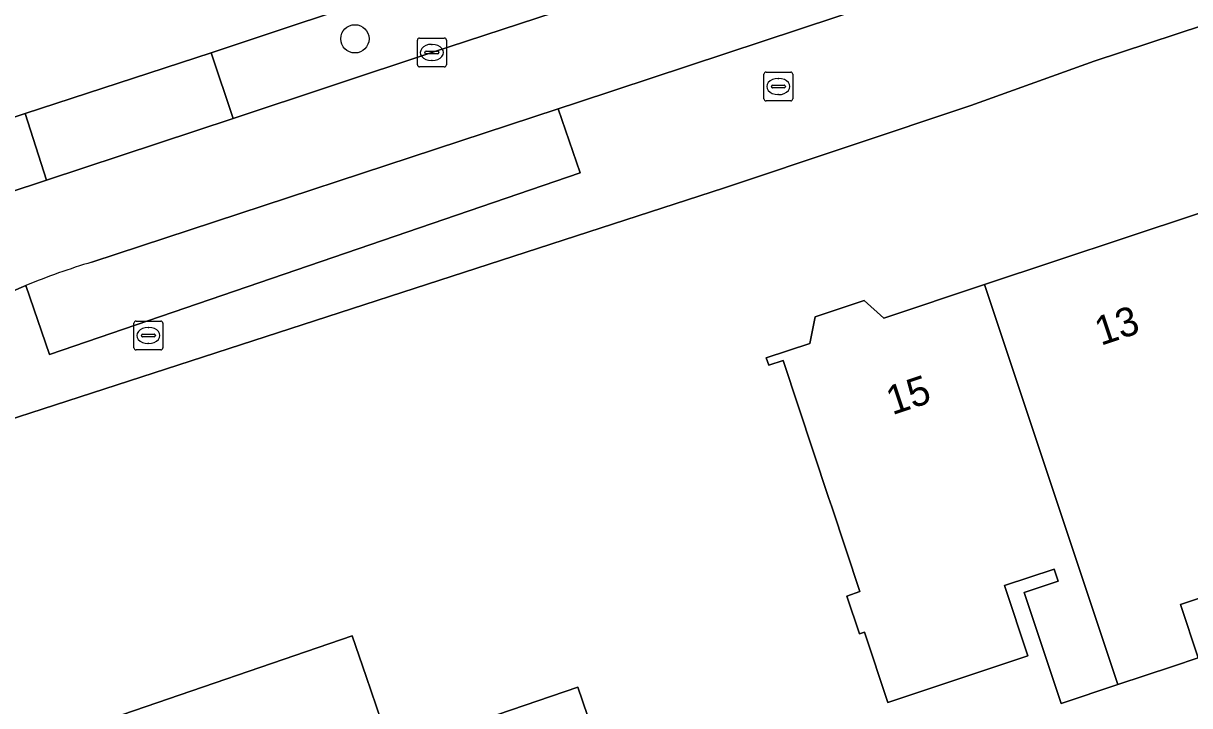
# Model space of a CAD drawing. Extents: x 161087 to 161926, y 382572 to 383873.
# Drawn here: x 161600.37 to 161640.73, y 382757.68 to 382781.29 of the extents above; entities that cross this region are included whole.
import ezdxf

# ---------------------------------------------------------------- set-up
doc = ezdxf.new("R2010")
doc.units = 0
for name, color, linetype in [('IMGEO_Berm_groen', 7, 'Continuous'), ('IMGEO_Boom', 7, 'Continuous'), ('IMGEO_Brandkraan', 7, 'Continuous'), ('IMGEO_Erf', 7, 'Continuous'), ('IMGEO_Fietspad_gesloten', 7, 'Continuous'), ('IMGEO_Kolk', 7, 'Continuous'), ('IMGEO_Muur', 7, 'Continuous'), ('IMGEO_Pand', 7, 'Continuous'), ('IMGEO_Pand_nummerreeks', 7, 'Continuous'), ('IMGEO_Rijbaan_lokaal_gesloten', 7, 'Continuous'), ('IMGEO_Rioolput', 7, 'Continuous'), ('IMGEO_Voetpad_halfverhard', 7, 'Continuous'), ('IMGEO_Voetpad_open', 7, 'Continuous')]:
    doc.layers.add(name, color=color, linetype=linetype)

msp = doc.modelspace()

# ---------------------------------------------------------------- linework, layer by layer
at = {"layer": 'IMGEO_Berm_groen'}
msp.add_lwpolyline([(161621.173, 382782.476), (161620.39, 382784.782), (161606.867, 382780.274), (161607.628, 382778.007), (161614.505, 382780.286)], close=True, dxfattribs=at)
for points in [[(161619.632, 382776.119), (161618.873, 382778.339), (161602.74, 382773.032)], [(161599.806, 382775.416), (161601.167, 382775.867), (161600.424, 382778.175), (161590.845, 382774.955)], [(161600.455, 382772.219), (161601.27, 382769.836), (161619.632, 382776.119)]]:
    msp.add_lwpolyline(points, dxfattribs=at)
msp.add_arc((161609.005, 382751.807), 22.13, 106.4443, 112.7267, dxfattribs=at)
at = {"layer": 'IMGEO_Boom'}
msp.add_circle((161611.84, 382780.758), 0.489, dxfattribs=at)
at = {"layer": 'IMGEO_Brandkraan'}
for p, q in [((161604.193, 382770.067), (161604.193, 382770.919)), ((161604.268, 382770.993), (161605.12, 382770.993)), ((161604.681, 382770.773), (161604.706, 382770.773)), ((161605.194, 382770.919), (161605.194, 382770.067)), ((161604.452, 382770.487), (161604.452, 382770.499)), ((161604.89, 382770.45), (161604.492, 382770.45)), ((161604.495, 382770.536), (161604.893, 382770.536)), ((161604.936, 382770.499), (161604.936, 382770.487)), ((161605.12, 382769.993), (161604.268, 382769.993)), ((161604.704, 382770.213), (161604.679, 382770.213))]:
    msp.add_line(p, q, dxfattribs=at)
for points in [[(161604.193, 382770.067), (161604.193, 382770.919)], [(161604.268, 382770.993), (161605.12, 382770.993)], [(161605.194, 382770.919), (161605.194, 382770.067)], [(161605.12, 382769.993), (161604.268, 382769.993)]]:
    msp.add_lwpolyline(points, dxfattribs=at)
for centre, radius, start, end in [((161604.27, 382770.917), 0.0765, 91.552, 178.448), ((161604.27, 382770.917), 0.0765, 91.552, 178.448), ((161605.118, 382770.917), 0.0765, 1.552, 88.448), ((161605.118, 382770.917), 0.0765, 1.552, 88.448), ((161604.492, 382770.496), 0.0403, 85.8775, 175.7526), ((161604.489, 382770.486), 0.0366, 178.938, 274.7102), ((161604.893, 382770.493), 0.043, 264.8664, 352.4533), ((161604.897, 382770.498), 0.0386, 1.7309, 96.639), ((161604.27, 382770.069), 0.0765, 181.552, 268.448), ((161604.27, 382770.069), 0.0765, 181.552, 268.448), ((161605.118, 382770.069), 0.0765, 271.552, 358.448), ((161605.118, 382770.069), 0.0765, 271.552, 358.448)]:
    msp.add_arc(centre, radius, start, end, dxfattribs=at)
for centre, major_axis, ratio, start_param, end_param in [((161604.68, 382770.493), (-0.387, 0.002), 0.722429, 4.712389, 7.853982), ((161604.705, 382770.493), (-0.39, 0.002), 0.717154, 1.570796, 4.712389)]:
    msp.add_ellipse(centre, major_axis=major_axis, ratio=ratio, start_param=start_param, end_param=end_param, dxfattribs=at)
at = {"layer": 'IMGEO_Erf'}
for points in [[(161667.594, 382789.929), (161637.427, 382779.982), (161633.162, 382778.456), (161624.636, 382775.599), (161601.023, 382767.942), (161596.158, 382766.372), (161596.018, 382766.327), (161595.848, 382766.199), (161596.009, 382765.952), (161595.696, 382765.813), (161595.594, 382766.012), (161590.565, 382762.379), (161588.667, 382761.008), (161586.678, 382759.589), (161585.017, 382758.404), (161585.099, 382758.295), (161583.93, 382757.469)], [(161644.492, 382762.54), (161640.411, 382761.181), (161641.024, 382759.339), (161640.133, 382759.042), (161638.239, 382758.411), (161636.283, 382757.76), (161635.004, 382761.604), (161636.175, 382761.994), (161636.037, 382762.407), (161634.326, 382761.838), (161635.133, 382759.413), (161630.282, 382757.798), (161629.474, 382760.224), (161629.3, 382760.166), (161628.864, 382761.475), (161629.318, 382761.634), (161628.343, 382764.561), (161628.236, 382764.882), (161626.657, 382769.626), (161626.163, 382769.462), (161626.079, 382769.715), (161627.585, 382770.216), (161627.773, 382771.134), (161629.469, 382771.698), (161630.151, 382771.093), (161633.634, 382772.252), (161641.001, 382774.705)]]:
    msp.add_lwpolyline(points, dxfattribs=at)
msp.add_lwpolyline([(161626.489, 382746.857), (161625.734, 382746.594), (161625.299, 382747.84), (161621.008, 382746.343), (161621.443, 382745.096), (161621.131, 382744.988), (161621.665, 382743.458), (161605.682, 382737.882), (161602.665, 382746.708), (161606.548, 382748.035), (161606.513, 382748.138), (161605.876, 382750), (161605.018, 382752.511), (161603.401, 382757.242), (161611.749, 382760.095), (161612.227, 382758.695), (161612.749, 382757.17), (161613.106, 382756.121), (161619.557, 382758.324), (161621.59, 382752.37), (161624.249, 382753.278)], close=True, dxfattribs=at)
at = {"layer": 'IMGEO_Fietspad_gesloten'}
msp.add_lwpolyline([(161590.845, 382774.955), (161600.424, 382778.175), (161606.867, 382780.274), (161620.39, 382784.782), (161636.138, 382789.999), (161645.193, 382792.972), (161647.376, 382793.71), (161647.995, 382793.914), (161673.571, 382802.349), (161674.047, 382802.506), (161679.239, 382804.225), (161681.775, 382805.065), (161703.785, 382812.521), (161709.459, 382814.438)], dxfattribs=at)
at = {"layer": 'IMGEO_Kolk'}
for p, q in [((161614.004, 382779.86), (161614.004, 382780.712)), ((161614.079, 382780.786), (161614.931, 382780.786)), ((161615.005, 382780.712), (161615.005, 382779.86)), ((161614.306, 382780.329), (161614.704, 382780.329)), ((161614.492, 382780.566), (161614.517, 382780.566)), ((161614.263, 382780.28), (161614.263, 382780.292)), ((161614.701, 382780.243), (161614.303, 382780.243)), ((161614.515, 382780.006), (161614.49, 382780.006)), ((161614.747, 382780.292), (161614.747, 382780.28)), ((161614.931, 382779.786), (161614.079, 382779.786))]:
    msp.add_line(p, q, dxfattribs=at)
for points in [[(161614.004, 382779.86), (161614.004, 382780.712)], [(161614.079, 382780.786), (161614.931, 382780.786)], [(161615.005, 382780.712), (161615.005, 382779.86)], [(161614.931, 382779.786), (161614.079, 382779.786)]]:
    msp.add_lwpolyline(points, dxfattribs=at)
for centre, radius, start, end in [((161614.081, 382780.71), 0.0765, 91.552, 178.448), ((161614.081, 382780.71), 0.0765, 91.552, 178.448), ((161614.929, 382780.71), 0.0765, 1.552, 88.448), ((161614.929, 382780.71), 0.0765, 1.552, 88.448), ((161614.303, 382780.289), 0.0403, 85.8775, 175.7526), ((161614.708, 382780.291), 0.0386, 1.7309, 96.639), ((161614.3, 382780.279), 0.0366, 178.938, 274.7102), ((161614.704, 382780.286), 0.043, 264.8664, 352.4533), ((161614.081, 382779.862), 0.0765, 181.552, 268.448), ((161614.081, 382779.862), 0.0765, 181.552, 268.448), ((161614.929, 382779.862), 0.0765, 271.552, 358.448), ((161614.929, 382779.862), 0.0765, 271.552, 358.448)]:
    msp.add_arc(centre, radius, start, end, dxfattribs=at)
for centre, major_axis, ratio, start_param, end_param in [((161614.491, 382780.286), (-0.387, 0.002), 0.722429, 4.712389, 7.853982), ((161614.516, 382780.286), (-0.39, 0.002), 0.717154, 1.570796, 4.712389)]:
    msp.add_ellipse(centre, major_axis=major_axis, ratio=ratio, start_param=start_param, end_param=end_param, dxfattribs=at)
at = {"layer": 'IMGEO_Muur'}
msp.add_lwpolyline([(161601.023, 382767.942), (161624.636, 382775.599)], dxfattribs=at)
at = {"layer": 'IMGEO_Pand'}
for points in [[(161643.603, 382769.478), (161643.358, 382770.215), (161641.778, 382774.958), (161641.001, 382774.705), (161633.634, 382772.252), (161638.239, 382758.411), (161640.133, 382759.042), (161641.024, 382759.339), (161640.411, 382761.181), (161644.492, 382762.54), (161643.696, 382764.929), (161644.2, 382765.097), (161644.979, 382765.344)], [(161633.634, 382772.252), (161630.151, 382771.093), (161629.469, 382771.698), (161627.773, 382771.134), (161627.585, 382770.216), (161626.079, 382769.715), (161626.163, 382769.462), (161626.657, 382769.626), (161628.236, 382764.882), (161628.343, 382764.561), (161629.318, 382761.634), (161628.864, 382761.475), (161629.3, 382760.166), (161629.474, 382760.224), (161630.282, 382757.798), (161635.133, 382759.413), (161634.326, 382761.838), (161636.037, 382762.407), (161636.175, 382761.994), (161635.004, 382761.604), (161636.283, 382757.76), (161638.239, 382758.411)], [(161624.249, 382753.278), (161621.59, 382752.37), (161619.557, 382758.324), (161613.106, 382756.121), (161612.749, 382757.17), (161612.227, 382758.695), (161611.749, 382760.095), (161603.401, 382757.242), (161605.018, 382752.511), (161605.876, 382750), (161606.513, 382748.138), (161606.548, 382748.035), (161602.665, 382746.708), (161605.682, 382737.882), (161621.665, 382743.458), (161621.131, 382744.988), (161621.443, 382745.096), (161621.008, 382746.343), (161625.299, 382747.84), (161625.734, 382746.594), (161626.489, 382746.857)]]:
    msp.add_lwpolyline(points, close=True, dxfattribs=at)
at = {"layer": 'IMGEO_Rijbaan_lokaal_gesloten'}
for points in [[(161602.74, 382773.032), (161618.873, 382778.339), (161619.539, 382778.558), (161637.495, 382784.499), (161640.402, 382785.458), (161656.819, 382790.909)], [(161645.919, 382790.64), (161636.843, 382787.626), (161630.206, 382785.442), (161626.567, 382784.247), (161621.173, 382782.476), (161614.505, 382780.286), (161607.628, 382778.007), (161601.167, 382775.867), (161599.806, 382775.416), (161588.34, 382771.632)], [(161599.434, 382771.772), (161599.942, 382772.001), (161600.455, 382772.219)]]:
    msp.add_lwpolyline(points, dxfattribs=at)
msp.add_arc((161609.005, 382751.807), 22.13, 106.4443, 112.7267, dxfattribs=at)
at = {"layer": 'IMGEO_Rioolput'}
for p, q in [((161625.995, 382778.682), (161625.995, 382779.534)), ((161626.07, 382779.608), (161626.922, 382779.608)), ((161626.996, 382779.534), (161626.996, 382778.682)), ((161626.254, 382779.102), (161626.254, 382779.114)), ((161626.297, 382779.151), (161626.695, 382779.151)), ((161626.483, 382779.388), (161626.508, 382779.388)), ((161626.738, 382779.114), (161626.738, 382779.102)), ((161626.692, 382779.065), (161626.294, 382779.065)), ((161626.506, 382778.828), (161626.481, 382778.828)), ((161626.922, 382778.608), (161626.07, 382778.608))]:
    msp.add_line(p, q, dxfattribs=at)
for points in [[(161625.995, 382778.682), (161625.995, 382779.534)], [(161626.07, 382779.608), (161626.922, 382779.608)], [(161626.996, 382779.534), (161626.996, 382778.682)], [(161626.922, 382778.608), (161626.07, 382778.608)]]:
    msp.add_lwpolyline(points, dxfattribs=at)
for centre, radius, start, end in [((161626.072, 382779.532), 0.0765, 91.552, 178.448), ((161626.072, 382779.532), 0.0765, 91.552, 178.448), ((161626.92, 382779.532), 0.0765, 1.552, 88.448), ((161626.92, 382779.532), 0.0765, 1.552, 88.448), ((161626.294, 382779.111), 0.0403, 85.8775, 175.7526), ((161626.291, 382779.101), 0.0366, 178.938, 274.7102), ((161626.695, 382779.108), 0.043, 264.8664, 352.4533), ((161626.699, 382779.113), 0.0386, 1.7309, 96.639), ((161626.072, 382778.684), 0.0765, 181.552, 268.448), ((161626.072, 382778.684), 0.0765, 181.552, 268.448), ((161626.92, 382778.684), 0.0765, 271.552, 358.448), ((161626.92, 382778.684), 0.0765, 271.552, 358.448)]:
    msp.add_arc(centre, radius, start, end, dxfattribs=at)
for centre, major_axis, ratio, start_param, end_param in [((161626.482, 382779.108), (-0.387, 0.002), 0.722429, 4.712389, 7.853982), ((161626.507, 382779.108), (-0.39, 0.002), 0.717154, 1.570796, 4.712389)]:
    msp.add_ellipse(centre, major_axis=major_axis, ratio=ratio, start_param=start_param, end_param=end_param, dxfattribs=at)
at = {"layer": 'IMGEO_Voetpad_halfverhard'}
msp.add_lwpolyline([(161606.867, 382780.274), (161600.424, 382778.175), (161601.167, 382775.867), (161607.628, 382778.007)], close=True, dxfattribs=at)
at = {"layer": 'IMGEO_Voetpad_open'}
for points in [[(161707.227, 382807.634), (161703.341, 382806.363), (161702.586, 382806.112), (161701.663, 382805.805), (161702.253, 382804.092), (161696.911, 382802.26), (161683.568, 382797.683), (161682.921, 382799.59), (161656.819, 382790.909), (161640.402, 382785.458), (161637.495, 382784.499), (161619.539, 382778.558), (161618.873, 382778.339), (161619.632, 382776.119), (161601.27, 382769.836), (161600.455, 382772.219), (161599.942, 382772.001), (161599.434, 382771.772)], [(161574.477, 382750.86), (161579.443, 382754.299), (161583.93, 382757.469), (161585.099, 382758.295), (161585.017, 382758.404), (161586.678, 382759.589), (161588.667, 382761.008), (161590.565, 382762.379), (161595.594, 382766.012), (161595.696, 382765.813), (161596.009, 382765.952), (161595.848, 382766.199), (161596.018, 382766.327), (161596.158, 382766.372), (161601.023, 382767.942), (161624.636, 382775.599), (161633.162, 382778.456), (161637.427, 382779.982), (161667.594, 382789.929), (161673.242, 382791.575), (161679.143, 382793.516), (161684.809, 382795.379)]]:
    msp.add_lwpolyline(points, dxfattribs=at)

# ---------------------------------------------------------------- texts
at = {"layer": 'IMGEO_Pand_nummerreeks'}
for s, rotation, p in [('13', 18.4149, (161637.655, 382770.134)), ('15', 18.4128, (161630.438, 382767.731))]:
    msp.add_text(s, height=1, rotation=rotation, dxfattribs=at).set_placement(p)

doc.saveas('drawing.dxf')
